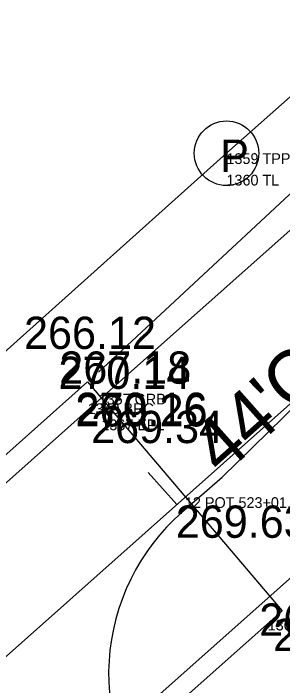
# Model space of a CAD drawing. Extents: x 49683 to 58852, y 49525 to 54803.
# Drawn here: x 53875.1 to 53900.1, y 51862.4 to 51924.9 of the extents above; entities that cross this region are included whole.
import ezdxf

# ---------------------------------------------------------------- set-up
doc = ezdxf.new("R2010")
doc.units = 0
for name, color, linetype in [('Level 1', 7, 'Continuous'), ('Level 11', 7, 'Continuous'), ('Level 18', 7, 'Continuous'), ('Level 3', 7, 'Continuous'), ('Level 32', 7, 'Continuous'), ('Level 48', 7, 'Continuous'), ('Level 5', 7, 'Continuous'), ('Level 51', 7, 'Continuous'), ('Level 53', 7, 'Continuous'), ('Level 55', 7, 'Continuous'), ('Level 57', 7, 'Continuous'), ('Level 59', 7, 'Continuous'), ('Level 61', 7, 'Continuous'), ('Level 7', 7, 'Continuous'), ('Level 9', 7, 'Continuous')]:
    doc.layers.add(name, color=color, linetype=linetype)

# ---------------------------------------------------------------- blocks, each defined once
blk = doc.blocks.new('TPP')
at = {"layer": 'Level 9'}
blk.add_circle((0, 0), 3, dxfattribs=at)
blk.add_text('P', height=3, dxfattribs=at).set_placement((-0.589, -1.729))

msp = doc.modelspace()

# ---------------------------------------------------------------- linework, layer by layer
at = {"layer": 'Level 1'}
for p, q in [((52544.807, 50683.302), (55534.583, 53340.862)), ((53890.278, 51879.268), (53887.621, 51882.257))]:
    msp.add_line(p, q, dxfattribs=at)
at = {"layer": 'Level 11'}
for p, q in [((53894.91, 51911.927), (54324.203, 52292.615)), ((53424.495, 51490.929), (53894.91, 51911.927))]:
    msp.add_line(p, q, dxfattribs=at)
at = {"layer": 'Level 18'}
for p, q in [((53894.5, 51881.812), (53921.658, 51908.457)), ((53890.773, 51878.547), (53894.5, 51881.812))]:
    msp.add_line(p, q, dxfattribs=at)
msp.add_arc((53903.952, 51863.502), 20, 131.2163, 221.63337, dxfattribs=at)
at = {"layer": 'Level 3'}
for p, q in [((53883.273, 51889.178), (54069.537, 52054.718)), ((53898.742, 51870.567), (54083.389, 52035.124)), ((53434.092, 51489.844), (53883.273, 51889.178)), ((53449.718, 51471.806), (53898.742, 51870.567))]:
    msp.add_line(p, q, dxfattribs=at)
at = {"layer": 'Level 5'}
for p, q in [((53432.563, 51491.203), (53881.993, 51890.68)), ((53881.993, 51890.68), (53900.074, 51869.402)), ((53900.074, 51869.402), (53451.19, 51470.163))]:
    msp.add_line(p, q, dxfattribs=at)
at = {"layer": 'Level 7'}
msp.add_line((53908.487, 51915.299), (53883.022, 51891.572), dxfattribs=at)

# ---------------------------------------------------------------- block references
at = {"layer": 'Level 9'}
msp.add_blockref('TPP', (53894.91, 51911.927), dxfattribs=at)

# ---------------------------------------------------------------- texts
at = {"layer": 'Level 32'}
for s, p in [('266.12', (53876.083, 51893.735)), ('267.18', (53879.362, 51890.501)), ('270.14', (53879.276, 51890.02)), ('270.16', (53880.858, 51886.67)), ('269.26', (53880.879, 51886.527)), ('269.34', (53882.324, 51884.982)), ('269.63', (53890.195, 51876.179)), ('269.36', (53897.959, 51867.074)), ('269.28', (53899.247, 51865.651))]:
    msp.add_text(s, height=3, dxfattribs=at).set_placement(p)
at = {"layer": 'Level 48'}
msp.add_text("44'C", height=5, rotation=41.63336, dxfattribs=at).set_placement((53894.5, 51881.812))
at = {"layer": 'Level 51'}
msp.add_text('12 POT 523+01.03', height=1, dxfattribs=at).set_placement((53891.047, 51878.951))
at = {"layer": 'Level 53'}
for s, p in [('1367 EPL', (53883.273, 51886.178)), ('1366 EPR', (53898.742, 51867.567))]:
    msp.add_text(s, height=1, dxfattribs=at).set_placement(p)
at = {"layer": 'Level 55'}
msp.add_text('1349 BRC', height=1, dxfattribs=at).set_placement((53881.993, 51887.68))
at = {"layer": 'Level 57'}
msp.add_text('1357 GRB', height=1, dxfattribs=at).set_placement((53883.022, 51888.572))
at = {"layer": 'Level 59'}
msp.add_text('1359 TPP', height=1, dxfattribs=at).set_placement((53894.91, 51910.927))
at = {"layer": 'Level 61'}
msp.add_text('1360 TL', height=1, dxfattribs=at).set_placement((53894.91, 51908.927))

doc.saveas('drawing.dxf')
